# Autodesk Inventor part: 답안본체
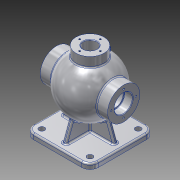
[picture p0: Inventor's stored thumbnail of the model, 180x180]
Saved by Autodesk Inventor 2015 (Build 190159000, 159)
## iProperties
Created: 2025-08
Part Number: 답안본체
Material: 알루미늄 6061
Document SubType Name: Modeling
Designer: USER
Density: 2.7 g/cm^3
Appearance: 알루미늄 - 평지
Mass: 1527.04 g
Surface Area: 1174.31 cm^2
Volume: 565.569 cm^3
Author: USER
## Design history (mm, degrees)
sketch "스케치1"
  geometry: L1 (-62.5, -62.5)-(62.5, -62.5); L2 (62.5, -62.5)-(62.5, 62.5); L3 (62.5, 62.5)-(-62.5, 62.5); L4 (-62.5, 62.5)-(-62.5, -62.5); L5 (-62.5, -62.5)-(62.5, 62.5); L6 (62.5, -62.5)-(-62.5, 62.5); 1 further point
  constraints: 12 end point, 2 midpoint, 2 parallel, 1 horizontal, 1 perpendicular
  dimensions: "d0" = 125 distance of L3.end L2.end; "d1" = 125 distance of L1.end L2.end
extrude "돌출1" new body sketch "스케치1" distance "d2" = 10; taper "d3" = 0 deg
fillet "모깎기1" dims "d4" = 16
sketch "스케치2"
  geometry: L1 (-4, 50.5)-(4, 50.5); L2 (4, 50.5)-(4, -50.5); L3 (4, -50.5)-(-4, -50.5); L4 (-4, -50.5)-(-4, 50.5); L5 (-50.5, 4)-(50.5, 4); L6 (50.5, 4)-(50.5, -4); L7 (50.5, -4)-(-50.5, -4); L8 (-50.5, -4)-(-50.5, 4); L9 (-62.5, 46.5)-(-62.5, -46.5) reference; L10 (62.5, -46.5)-(62.5, 46.5) reference; L11 (46.5, 62.5)-(-46.5, 62.5) reference; L12 (-46.5, -62.5)-(46.5, -62.5) reference; L13 (0, 0)-(0, 50.5); L14 (0, 0)-(50.5, 0); 2 further points
  constraints: 20 end point, 5 parallel, 4 midpoint, 3 horizontal, 2 perpendicular, 1 horizontal alignment, 1 vertical alignment
  dimensions: "d5" = 8 distance of L1.start L1.end; "d6" = 8 distance of L5.end L6.end; "d7" = 12 distance between parallel lines of L8 L9; "d8" = 12 distance between parallel lines of L10 L6; "d9" = 12 distance between parallel lines of L11 L1; "d10" = 12 distance between parallel lines of L12 L3
extrude "돌출2" join sketch "스케치2" distance "d11" = 85; taper "d12" = 0 deg
feature "면 기울기1" dims angle "d13" = 20 deg
node "작업 평면1"
sketch "스케치3"
  geometry: L1 (4, 23.202)-(4, 4) reference; L2 (4, 4)-(23.202, 4) reference; L3 (23.202, 4)-(23.202, -4) reference; L4 (23.202, -4)-(4, -4) reference; L5 (4, -4)-(4, -23.202) reference; L6 (4, -23.202)-(-4, -23.202) reference; L7 (-4, -23.202)-(-4, -4) reference; L8 (-4, -4)-(-23.202, -4) reference; L9 (-23.202, -4)-(-23.202, 4) reference; L10 (-23.202, 4)-(-4, 4) reference; L11 (-4, 4)-(-4, 23.202) reference; L12 (-4, 23.202)-(4, 23.202) reference; L13 (-46.5, 62.5)-(46.5, 62.5) reference; L14 (46.5, -62.5)-(-46.5, -62.5) reference; L15 (0, 54)-(0, -54); A1 r 54 centre (0, 0) between (0, 54) and (0, -54); 1 further point
  constraints: 2 end point, 2 point on circle, 1 centre point, 1 coincident
  dimensions: "d15" = 108 diameter of A1
revolve "회전1" sketch "스케치3" stored, may be unused: angle "d16" = 90 deg
node "작업 평면2"
sketch "스케치5"
  geometry: L1 (4, 46.186)-(4, 31.297) reference; L2 (-4, 31.297)-(-4, 46.186) reference; L3 (-37.329, 46.186)-(-37.329, 46.186) reference; L4 (-4, 46.186)-(-4, 31.297) reference; L5 (4, 31.297)-(4, 46.186) reference; L6 (37.329, 46.186)-(37.329, 46.186) reference; C1 r 31 at (0, 85); A1 r 53.852 centre (0, 85) between (4, 31.297) and (37.329, 46.186) reference; A2 r 53.852 centre (0, 85) between (-37.329, 46.186) and (-4, 31.297) reference; A3 r 53.852 centre (0, 85) between (-37.329, 46.186) and (-4, 31.297) reference; A4 r 53.852 centre (0, 85) between (4, 31.297) and (37.329, 46.186) reference; 3 further points; 2 other entities
  constraints: 1 centre point, 1 coincident, 2 other
  dimensions: "d18" = 62 diameter of C1
extrude "돌출3" join sketch "스케치5" distance "d19" = 130; taper "d20" = 0 deg
node "작업 평면3"
sketch "스케치6"
  geometry: C1 r 27 at (0, 0); 1 further point
  constraints: 1 centre point, 1 coincident
  dimensions: "d22" = 54 diameter of C1
extrude "돌출4" join sketch "스케치6" distance "d23" = 50; taper "d24" = 0 deg
sketch "스케치7"
  geometry: L1 (-27, 131.765)-(27, 131.765) reference; L2 (44.215, 116)-(44.215, 54) reference; L3 (-44.215, 54)-(-44.215, 116) reference; L4 (4, 31.297)-(4, 46.186) reference; L5 (37.329, 46.186)-(37.329, 46.186) reference; L6 (4, 46.186)-(4, 31.297) reference; L7 (-4, 31.297)-(-4, 46.186) reference; L8 (-37.329, 46.186)-(-37.329, 46.186) reference; L9 (-4, 46.186)-(-4, 31.297) reference; L10 (-27, 131.765)-(27, 131.765) reference; L11 (0, 41)-(0, 129); L12 (0, 138.852)-(0, 138.88); A1 r 53.852 centre (0, 85) between (4, 31.297) and (37.329, 46.186) reference; A2 r 53.852 centre (0, 85) between (4, 31.297) and (37.329, 46.186) reference; A3 r 53.852 centre (0, 85) between (-37.329, 46.186) and (-4, 31.297) reference; A4 r 53.852 centre (0, 85) between (-37.329, 46.186) and (-4, 31.297) reference; A5 r 44 centre (0, 85) between (0, 41) and (0, 129); 3 further points; 2 other entities
  constraints: 4 end point, 3 point on circle, 2 perpendicular, 1 centre point, 1 coincident, 1 midpoint, 3 other
  dimensions: "d25" = 88 diameter of A5
revolve "회전2" sketch "스케치7" stored, may be unused: angle "d26" = 90 deg
hole "구멍1" diameter "d29" = 30; stored, may be unused: countersink angle "d33" = 90 deg, drill point angle "d35" = 0 deg; dims "d27" = 10, "d28" = 10, "d30" = 6, "d31" = 35, "d32" = 16, "d34" = 8
hole "구멍2" diameter "d38" = 26; stored, may be unused: countersink angle "d42" = 90 deg, drill point angle "d44" = 0 deg; dims "d36" = 10, "d37" = 10, "d39" = 6, "d40" = 35, "d41" = 16, "d43" = 70
sketch "스케치8"
  geometry: L1 (0, 0)-(20, 0)
  constraints: 2 end point, 1 horizontal
  dimensions: "d45" = 20 distance of L1.start L1.end
hole "구멍3" sketch "스케치8" at (20, 0) diameter "d46" = 3.242; stored, may be unused: countersink angle "d50" = 90 deg, drill point angle "d52" = 118 deg; dims "d47" = 9, "d48" = 35, "d49" = 16, "d51" = 11
sketch "스케치9"
  geometry: L1 (0, 0)-(0, 24); C1 r 15 at (0, 0) reference; C2 r 17.5 at (0, 0) reference; 1 further point
  constraints: 2 end point, 1 vertical
  dimensions: "d56" = 24 distance of L1.start L1.end
hole "구멍4" sketch "스케치9" diameter "d57" = 3.242; stored, may be unused: countersink angle "d61" = 90 deg, drill point angle "d63" = 118 deg; dims "d58" = 12, "d59" = 35, "d60" = 16, "d62" = 15
sketch "스케치10"
  geometry: L1 (-13, 150)-(13, 150) reference; A1 r 54 centre (0, 85) between (37.385, 46.034) and (-37.385, 46.034) reference; 2 further points
  constraints: 1 vertical alignment, 1 other
  dimensions: "d67" = 9 distance from line of L1 point (0, 141)
feature "엠보싱1" sketch "스케치10" dims "d0" = 125, "d1" = 125, "d68" = 1, "d69" = 0
sketch "스케치11"
  geometry: L1 (-46.5, 46.5)-(46.5, 46.5); L2 (46.5, 46.5)-(46.5, -46.5); L3 (46.5, -46.5)-(-46.5, -46.5); L4 (-46.5, -46.5)-(-46.5, 46.5); L5 (-46.5, 46.5)-(46.5, -46.5); L6 (46.5, 46.5)-(-46.5, -46.5); 1 further point
  constraints: 12 end point, 2 midpoint, 2 parallel, 1 horizontal, 1 perpendicular
  dimensions: "d70" = 93 distance of L2.end L3.end; "d71" = 93 distance of L1.end L2.end
hole "구멍5" sketch "스케치11" at (-46.5, 46.5) diameter "d72" = 11; stored, may be unused: countersink angle "d76" = 90 deg, drill point angle "d78" = 0 deg; dims "d73" = 12, "d74" = 35, "d75" = 16, "d77" = 15
fillet "모깎기2" dims "d85" = 3
fillet "모깎기3" dims "d86" = 3
fillet "모깎기4" dims "d87" = 3
fillet "모깎기5" dims "d88" = 3
chamfer "모따기1" distance "d89" = 1; stored, may be unused: second distance "d90" = 2, angle "d91" = 45 deg
fillet "모깎기6" dims "d95" = 0.6
node "솔리드1"
mirror "대칭1"
pattern_circular "원형 패턴1" dims angle "d54" = 360 deg
pattern_circular "원형 패턴2" dims angle "d65" = 360 deg
mirror "대칭3"
pattern_linear "직사각형 패턴1" dims "d81" = 93, "d84" = 93
node "투영된 루프1"
node "투영된 루프2"
node "절단 모서리 투영1"
other parameters: "d14" = -85, "d17" = 65
